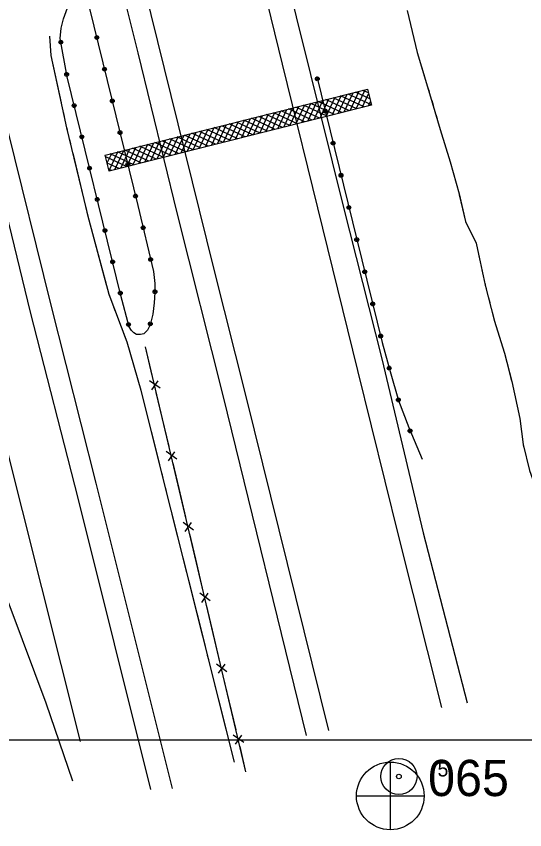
# Model space of a CAD drawing. Extents: x 353423 to 364002, y 127000 to 201942.
# Drawn here: x 362186.7 to 362397.2, y 127462.8 to 127799.5 of the extents above; entities that cross this region are included whole.
import ezdxf

# ---------------------------------------------------------------- set-up
doc = ezdxf.new("R2010")
doc.units = 0
for name, color, linetype in [('E_DTM_SlopeBottom', 7, 'Continuous'), ('E_DTM_SlopeTop', 7, 'Continuous'), ('E_LAND_BrushLine', 7, 'Continuous'), ('E_LAND_TreeLine', 7, 'Continuous'), ('E_MISCPROP', 7, 'Continuous'), ('E_RDWY_AsphConc', 7, 'Continuous'), ('E_RDWY_Gravel', 7, 'Continuous'), ('E_STRUCT_WingWall', 7, 'Continuous')]:
    doc.layers.add(name, color=color, linetype=linetype)

msp = doc.modelspace()

# ---------------------------------------------------------------- linework, layer by layer
at = {"layer": 'E_DTM_SlopeBottom'}
for p, q in [((362246.21, 127645.5), (362241.87, 127648.6)), ((362242.76, 127644.87), (362245.4, 127648.6)), ((362253.14, 127616.18), (362248.81, 127619.29)), ((362249.69, 127615.55), (362252.33, 127619.28)), ((362260.08, 127586.86), (362255.74, 127589.97)), ((362256.62, 127586.23), (362259.27, 127589.96)), ((362267.01, 127557.54), (362262.67, 127560.65)), ((362263.56, 127556.92), (362266.2, 127560.65)), ((362273.94, 127528.22), (362269.61, 127531.33)), ((362270.49, 127527.6), (362273.13, 127531.33)), ((362280.88, 127498.91), (362276.54, 127502.01)), ((362277.42, 127498.28), (362280.07, 127502.01))]:
    msp.add_line(p, q, dxfattribs=at)
for points in [[(362281.81, 127486.77), (362240.21, 127662.68)], [(362243.03, 127650.77), (362240.21, 127662.68)], [(362247.15, 127633.37), (362244.67, 127643.84)], [(362249.96, 127621.45), (362247.15, 127633.37)], [(362254.08, 127604.05), (362251.6, 127614.53)], [(362256.9, 127592.13), (362254.08, 127604.05)], [(362261.01, 127574.73), (362258.53, 127585.21)], [(362263.83, 127562.82), (362261.01, 127574.73)], [(362267.95, 127545.41), (362265.47, 127555.89)], [(362270.76, 127533.5), (362267.95, 127545.41)], [(362274.88, 127516.09), (362272.4, 127526.57)], [(362277.7, 127504.18), (362274.88, 127516.09)], [(362281.81, 127486.77), (362279.34, 127497.25)]]:
    msp.add_lwpolyline(points, dxfattribs=at)
at = {"layer": 'E_DTM_SlopeTop'}
for points in [[(361986.96, 129308.18), (362011.95, 129186.04), (362034, 129078.52), (362056.35, 128972.18), (362075.26, 128880.33), (362094.46, 128785.72), (362115.22, 128687.95), (362130.71, 128615.46), (362145.67, 128539.64), (362162.83, 128460.27), (362181.67, 128374.15), (362198.45, 128291.18), (362218.54, 128189.69), (362234.81, 128110.4), (362253.24, 128026.48), (362276.57, 127918.01), (362296.66, 127823.22), (362308.56, 127775.45), (362322.07, 127720.86), (362338.07, 127657.68)], [(362362.9, 127513.34), (362345.1, 127584.24), (362328.1, 127652.84), (362313.6, 127711.8), (362296.96, 127779.66), (362282.73, 127837.96), (362269.18, 127893.76), (362250.84, 127977.26), (362238.21, 128037.73), (362226.99, 128091.45), (362210.34, 128173.73), (362197.11, 128239.57), (362184.84, 128299.68), (362169.78, 128373.93), (362152.87, 128456.81), (362138.01, 128526.39), (362123.24, 128598.99), (362106.14, 128682.62), (362088.32, 128769.09), (362075.19, 128833.71), (362063.83, 128889.32), (362047.62, 128969.62), (362032.36, 129043.34)], [(362213.36, 127499.38), (362181.32, 127626.78), (362161.72, 127704.48), (362145.67, 127768.24), (362130.29, 127831.43), (362114.83, 127893.38), (362099.46, 127954.81), (362080.71, 128029.42), (362060.68, 128112.08), (362041.03, 128191.06), (362025.12, 128255.61), (362009.2, 128316.48), (361993.37, 128377.95), (361983.36, 128416.15), (361965.4, 128481.36), (361942.93, 128556.66), (361920.14, 128628), (361900.6, 128685.51), (361876.59, 128752.15), (361856.16, 128806.29), (361823.66, 128886.96), (361789.69, 128966.2), (361770.78, 129008.39)], [(362242.46, 127479.5), (362212.32, 127600.03), (362192.55, 127677.03), (362174.72, 127750.39), (362155.56, 127826.22), (362139.47, 127892.39), (362124.1, 127954.15), (362107.18, 128021.4), (362083.5, 128117.26), (362065.27, 128192.51), (362039.09, 128294.93), (362007.13, 128419.6), (361987.58, 128490.18), (361965.39, 128564.32), (361949.96, 128613.11), (361928.85, 128676.38), (361908.85, 128733.26), (361886.38, 128793.04), (361860.05, 128860.65), (361830.57, 128932.61), (361797.13, 129007.43)], [(362306.82, 127501.81), (362272.46, 127642.02), (362253.36, 127718.15), (362237.11, 127784.36), (362217.92, 127861.21), (362202.38, 127923.46), (362185.34, 127989.74), (362165.29, 128069.8), (362142.52, 128162.86), (362122.2, 128245.55), (362093.09, 128360.53), (362068.17, 128453.81), (362054.88, 128503.33), (362043.46, 128543.58), (362036.29, 128568.96), (362026.53, 128600.5), (362015.49, 128635.47), (361996.52, 128689.52), (361978.48, 128738.95), (361954.64, 128800.32), (361930.11, 128861.39), (361909.42, 128910.29), (361890.21, 128953.79), (361874.92, 128987.28)], [(362316.06, 127503.9), (362281.84, 127642.16), (362268.56, 127695.28), (362250.81, 127766.73), (362231.53, 127845.06)], [(362057.27, 127838.63), (362082.93, 127788.62), (362095.76, 127762.34), (362110.65, 127731.02), (362120.04, 127710), (362140.34, 127663.88), (362166.72, 127600.42), (362184.46, 127554.16), (362198.99, 127515.34), (362209.92, 127483.05)], [(362251.33, 127479.89), (362219.83, 127606.24), (362201.15, 127679.92), (362183.03, 127752.98), (362165.42, 127823.24)], [(362338.07, 127657.68), (362355.17, 127585.72), (362373.34, 127515.28)]]:
    msp.add_lwpolyline(points, dxfattribs=at)
at = {"layer": 'E_LAND_BrushLine'}
for p, q in [((362324.96, 127760.5), (362328.67, 127768.46)), ((362327.46, 127761.13), (362331.17, 127769.09)), ((362332.46, 127767.78), (362330.19, 127768.84)), ((362312.46, 127757.37), (362316.17, 127765.32)), ((362314.96, 127757.99), (362318.67, 127765.95)), ((362317.46, 127758.62), (362321.17, 127766.58)), ((362327.68, 127761.19), (362317.88, 127765.75)), ((362319.96, 127759.25), (362323.67, 127767.21)), ((362330.75, 127761.96), (362320.96, 127766.52)), ((362322.46, 127759.88), (362326.17, 127767.83)), ((362333.72, 127762.78), (362324.04, 127767.3)), ((362333.09, 127765.28), (362327.11, 127768.07)), ((362329.96, 127761.76), (362332.57, 127767.35)), ((362299.97, 127754.23), (362303.68, 127762.18)), ((362302.47, 127754.86), (362306.18, 127762.81)), ((362312.3, 127757.32), (362302.5, 127761.89)), ((362304.97, 127755.48), (362308.68, 127763.44)), ((362315.37, 127758.1), (362305.58, 127762.66)), ((362307.47, 127756.11), (362311.17, 127764.07)), ((362318.45, 127758.87), (362308.66, 127763.43)), ((362309.97, 127756.74), (362313.67, 127764.7)), ((362321.52, 127759.64), (362311.73, 127764.21)), ((362324.6, 127760.41), (362314.81, 127764.98)), ((362332.46, 127762.39), (362333.34, 127764.28)), ((362284.97, 127750.46), (362288.68, 127758.42)), ((362287.47, 127751.09), (362291.18, 127759.05)), ((362289.97, 127751.72), (362293.68, 127759.68)), ((362299.99, 127754.24), (362290.2, 127758.8)), ((362292.47, 127752.35), (362296.18, 127760.3)), ((362303.07, 127755.01), (362293.28, 127759.57)), ((362294.97, 127752.97), (362298.68, 127760.93)), ((362306.14, 127755.78), (362296.35, 127760.35)), ((362297.47, 127753.6), (362301.18, 127761.56)), ((362309.22, 127756.55), (362299.43, 127761.12)), ((362272.47, 127747.33), (362276.18, 127755.28)), ((362274.97, 127747.95), (362278.68, 127755.91)), ((362277.47, 127748.58), (362281.18, 127756.54)), ((362287.69, 127751.15), (362277.89, 127755.71)), ((362279.97, 127749.21), (362283.68, 127757.17)), ((362290.76, 127751.92), (362280.97, 127756.48)), ((362282.47, 127749.84), (362286.18, 127757.79)), ((362293.84, 127752.69), (362284.05, 127757.26)), ((362296.91, 127753.46), (362287.12, 127758.03)), ((362259.98, 127744.19), (362263.69, 127752.15)), ((362262.48, 127744.82), (362266.19, 127752.77)), ((362272.3, 127747.28), (362262.51, 127751.85)), ((362264.98, 127745.45), (362268.69, 127753.4)), ((362275.38, 127748.06), (362265.59, 127752.62)), ((362267.48, 127746.07), (362271.19, 127754.03)), ((362278.46, 127748.83), (362268.66, 127753.4)), ((362269.98, 127746.7), (362273.68, 127754.65)), ((362281.53, 127749.6), (362271.74, 127754.17)), ((362284.61, 127750.37), (362274.82, 127754.94)), ((362244.98, 127740.43), (362248.69, 127748.38)), ((362247.48, 127741.05), (362251.19, 127749.01)), ((362249.98, 127741.68), (362253.69, 127749.64)), ((362260, 127744.2), (362250.21, 127748.76)), ((362252.48, 127742.31), (362256.19, 127750.26)), ((362263.08, 127744.97), (362253.28, 127749.53)), ((362254.98, 127742.93), (362258.69, 127750.89)), ((362266.15, 127745.74), (362256.36, 127750.31)), ((362257.48, 127743.56), (362261.19, 127751.52)), ((362269.23, 127746.51), (362259.44, 127751.08)), ((362232.48, 127737.29), (362236.2, 127745.24)), ((362244.62, 127740.33), (362234.83, 127744.9)), ((362234.98, 127737.92), (362238.69, 127745.87)), ((362237.48, 127738.54), (362241.19, 127746.5)), ((362247.7, 127741.11), (362237.9, 127745.67)), ((362239.98, 127739.17), (362243.69, 127747.13)), ((362250.77, 127741.88), (362240.98, 127746.45)), ((362242.48, 127739.8), (362246.19, 127747.75)), ((362253.85, 127742.65), (362244.06, 127747.22)), ((362256.92, 127743.42), (362247.13, 127747.99)), ((362223.58, 127741.85), (362223.7, 127742.11)), ((362224.35, 127738.77), (362226.2, 127742.73)), ((362225.12, 127735.69), (362228.7, 127743.36)), ((362235.39, 127738.02), (362225.6, 127742.58)), ((362227.49, 127736.03), (362231.2, 127743.99)), ((362238.47, 127738.79), (362228.67, 127743.35)), ((362229.98, 127736.66), (362233.7, 127744.62)), ((362241.54, 127739.56), (362231.75, 127744.13)), ((362232.32, 127737.25), (362223.73, 127741.25)), ((362229.24, 127736.47), (362224.35, 127738.75)), ((362226.16, 127735.7), (362224.98, 127736.25))]:
    msp.add_line(p, q, dxfattribs=at)
msp.add_lwpolyline([(362223.52, 127742.06), (362332.08, 127769.32), (362333.74, 127762.71), (362225.18, 127735.45)], close=True, dxfattribs=at)
at = {"layer": 'E_LAND_TreeLine'}
msp.add_line((360500, 127500), (363500, 127500), dxfattribs=at)
at = {"layer": 'E_MISCPROP'}
for points in [[(362207.72, 127774.48), (362204.89, 127790.3), (362205.25, 127794.6), (362206.24, 127798.43), (362207.95, 127802.93)], [(362207.72, 127774.48), (362204.89, 127790.3), (362205.25, 127794.6), (362206.24, 127798.43), (362207.95, 127802.93)], [(362217.09, 127802.76), (362237.03, 127721.24), (362243.52, 127693.8), (362244.06, 127688.9), (362244.12, 127685.1), (362243.83, 127680.94), (362243.21, 127676.21), (362242.11, 127671.78), (362241.04, 127669.55), (362239.45, 127668.07), (362238.09, 127667.79), (362236.47, 127667.76), (362235.36, 127668.43), (362234.41, 127669.43), (362233.42, 127671.02), (362230.03, 127683.99)], [(362217.09, 127802.76), (362237.03, 127721.24), (362243.52, 127693.8), (362244.06, 127688.9), (362244.12, 127685.1), (362243.83, 127680.94), (362243.21, 127676.21), (362242.11, 127671.78), (362241.04, 127669.55), (362239.45, 127668.07), (362238.09, 127667.79), (362236.47, 127667.76), (362235.36, 127668.43), (362234.41, 127669.43), (362233.42, 127671.02), (362230.03, 127683.99)], [(362230.03, 127683.99), (362207.72, 127774.48)], [(362230.03, 127683.99), (362207.72, 127774.48)], [(362311.09, 127774.59), (362327.66, 127707.11), (362338.23, 127664.49), (362341.47, 127652.4), (362344.96, 127640.5), (362349.16, 127629.26), (362354.71, 127616.2)], [(362311.09, 127774.59), (362327.66, 127707.11), (362338.23, 127664.49), (362341.47, 127652.4), (362344.96, 127640.5), (362349.16, 127629.26), (362354.71, 127616.2)]]:
    msp.add_lwpolyline(points, dxfattribs=at)
for centre, radius in [((362205.16, 127788.75), 0.786), ((362205.16, 127788.75), 0.396), ((362220.05, 127790.68), 0.786), ((362220.05, 127790.68), 0.396), ((362207.54, 127775.45), 0.786), ((362207.54, 127775.45), 0.396), ((362223.25, 127777.57), 0.786), ((362223.25, 127777.57), 0.396), ((362311.33, 127773.61), 0.798), ((362311.33, 127773.61), 0.402), ((362226.46, 127764.45), 0.786), ((362210.67, 127762.5), 0.775), ((362210.67, 127762.5), 0.391), ((362226.46, 127764.45), 0.396), ((362314.6, 127760.3), 0.798), ((362314.6, 127760.3), 0.402), ((362229.67, 127751.33), 0.786), ((362229.67, 127751.33), 0.396), ((362213.86, 127749.57), 0.775), ((362213.86, 127749.57), 0.391), ((362317.87, 127746.98), 0.798), ((362317.87, 127746.98), 0.402), ((362232.87, 127738.22), 0.786), ((362232.87, 127738.22), 0.396), ((362217.04, 127736.65), 0.775), ((362217.04, 127736.65), 0.391), ((362321.14, 127733.67), 0.798), ((362321.14, 127733.67), 0.402), ((362236.08, 127725.1), 0.786), ((362236.08, 127725.1), 0.396), ((362220.23, 127723.72), 0.775), ((362220.23, 127723.72), 0.391), ((362324.4, 127720.36), 0.798), ((362324.4, 127720.36), 0.402), ((362223.42, 127710.79), 0.775), ((362239.22, 127711.97), 0.786), ((362239.22, 127711.97), 0.396), ((362223.42, 127710.79), 0.391), ((362327.67, 127707.04), 0.798), ((362327.67, 127707.04), 0.402), ((362226.6, 127697.87), 0.775), ((362226.6, 127697.87), 0.391), ((362242.33, 127698.83), 0.786), ((362242.33, 127698.83), 0.396), ((362330.97, 127693.74), 0.798), ((362330.97, 127693.74), 0.402), ((362229.79, 127684.94), 0.775), ((362229.79, 127684.94), 0.391), ((362244.12, 127685.5), 0.786), ((362244.12, 127685.5), 0.396), ((362334.27, 127680.43), 0.798), ((362334.27, 127680.43), 0.402), ((362233.19, 127671.89), 0.786), ((362233.19, 127671.89), 0.396), ((362242.2, 127672.17), 0.786), ((362242.2, 127672.17), 0.396), ((362337.57, 127667.13), 0.798), ((362337.57, 127667.13), 0.402), ((362341.08, 127653.87), 0.798), ((362341.08, 127653.87), 0.402), ((362344.9, 127640.71), 0.798), ((362344.9, 127640.71), 0.402), ((362349.74, 127627.88), 0.798), ((362349.74, 127627.88), 0.402)]:
    msp.add_circle(centre, radius, dxfattribs=at)
at = {"layer": 'E_RDWY_AsphConc'}
for radius in [7.5, 0.96]:
    msp.add_circle((362345.11, 127484.84), radius, dxfattribs=at)
at = {"layer": 'E_RDWY_Gravel'}
for p, q in [((362341.5, 127490.83), (362341.43, 127462.97)), ((362327.59, 127476.8), (362355.49, 127476.78))]:
    msp.add_line(p, q, dxfattribs=at)
msp.add_circle((362341.55, 127476.8), 14, dxfattribs=at)
at = {"layer": 'E_STRUCT_WingWall'}
for points in [[(362348.5, 127801.91), (362352.71, 127784.56), (362357.84, 127767.54), (362362.26, 127752.66), (362366.35, 127739.21), (362370.04, 127725.96), (362372.69, 127714.56), (362377.04, 127705.6), (362380.86, 127688.24), (362384.6, 127673.69), (362388.79, 127660), (362391.85, 127648.28), (362395.13, 127632.98), (362396.49, 127622.24), (362399.23, 127611.47), (362403.56, 127599.18), (362407.92, 127586.69), (362410.97, 127577.26), (362414.17, 127565.24)], [(362348.52, 127801.83), (362352.71, 127784.56), (362355.87, 127774.08)], [(362277.02, 127490.75), (362250.84, 127595.06), (362238.46, 127644.64), (362232.56, 127664.63), (362225.22, 127684.31), (362216.85, 127715.12), (362207.69, 127753.37), (362201.12, 127783.3), (362200.57, 127791.33)], [(362205.43, 127763.68), (362201.12, 127783.3), (362200.57, 127791.33)], [(362357.01, 127770.28), (362357.58, 127768.39)], [(362358.71, 127764.59), (362359.28, 127762.7)], [(362206.67, 127758), (362206.26, 127759.89)], [(362360.41, 127758.9), (362360.97, 127757.01)], [(362207.94, 127752.32), (362207.69, 127753.37), (362207.51, 127754.21)], [(362362.1, 127753.21), (362362.26, 127752.66), (362366.35, 127739.21), (362370.04, 127725.96), (362370.11, 127725.65)], [(362209.3, 127746.66), (362208.85, 127748.54)], [(362216.75, 127715.52), (362210.2, 127742.88)], [(362370.11, 127725.65), (362372.69, 127714.56), (362377.04, 127705.6), (362378.63, 127698.39)], [(362224.11, 127688.37), (362216.85, 127715.12), (362216.75, 127715.52)], [(362379.48, 127694.53), (362379.91, 127692.59)], [(362380.76, 127688.72), (362380.86, 127688.24), (362381.23, 127686.8)], [(362225.78, 127682.79), (362225.22, 127684.31), (362225.13, 127684.62)], [(362382.22, 127682.96), (362382.71, 127681.04)], [(362227.82, 127677.34), (362227.14, 127679.16)], [(362383.7, 127677.21), (362384.6, 127673.69), (362388.79, 127660), (362391.51, 127649.57)], [(362229.85, 127671.89), (362229.18, 127673.71)], [(362239.29, 127641.32), (362238.46, 127644.64), (362232.56, 127664.63), (362231.21, 127668.25)], [(362391.51, 127649.57), (362391.85, 127648.28), (362395.13, 127632.98), (362396.49, 127622.24), (362396.72, 127621.35)], [(362246.11, 127614.02), (362239.29, 127641.32)], [(362247.52, 127608.37), (362247.05, 127610.26)], [(362248.93, 127602.73), (362248.46, 127604.61)], [(362250.34, 127597.08), (362249.87, 127598.96)], [(362258.13, 127566.03), (362251.28, 127593.31)], [(362264.98, 127538.74), (362258.13, 127566.03)], [(362266.39, 127533.09), (362265.92, 127534.97)], [(362267.81, 127527.45), (362267.34, 127529.33)], [(362269.22, 127521.8), (362268.75, 127523.68)], [(362277.02, 127490.75), (362270.17, 127518.04)]]:
    msp.add_lwpolyline(points, dxfattribs=at)

# ---------------------------------------------------------------- texts
at = {"layer": 'E_RDWY_AsphConc'}
msp.add_text('5', height=6, dxfattribs=at).set_placement((362361.11, 127484.84))
at = {"layer": 'E_RDWY_Gravel'}
msp.add_text('065', height=15, dxfattribs=at).set_placement((362357.2, 127476.73))

doc.saveas('drawing.dxf')
